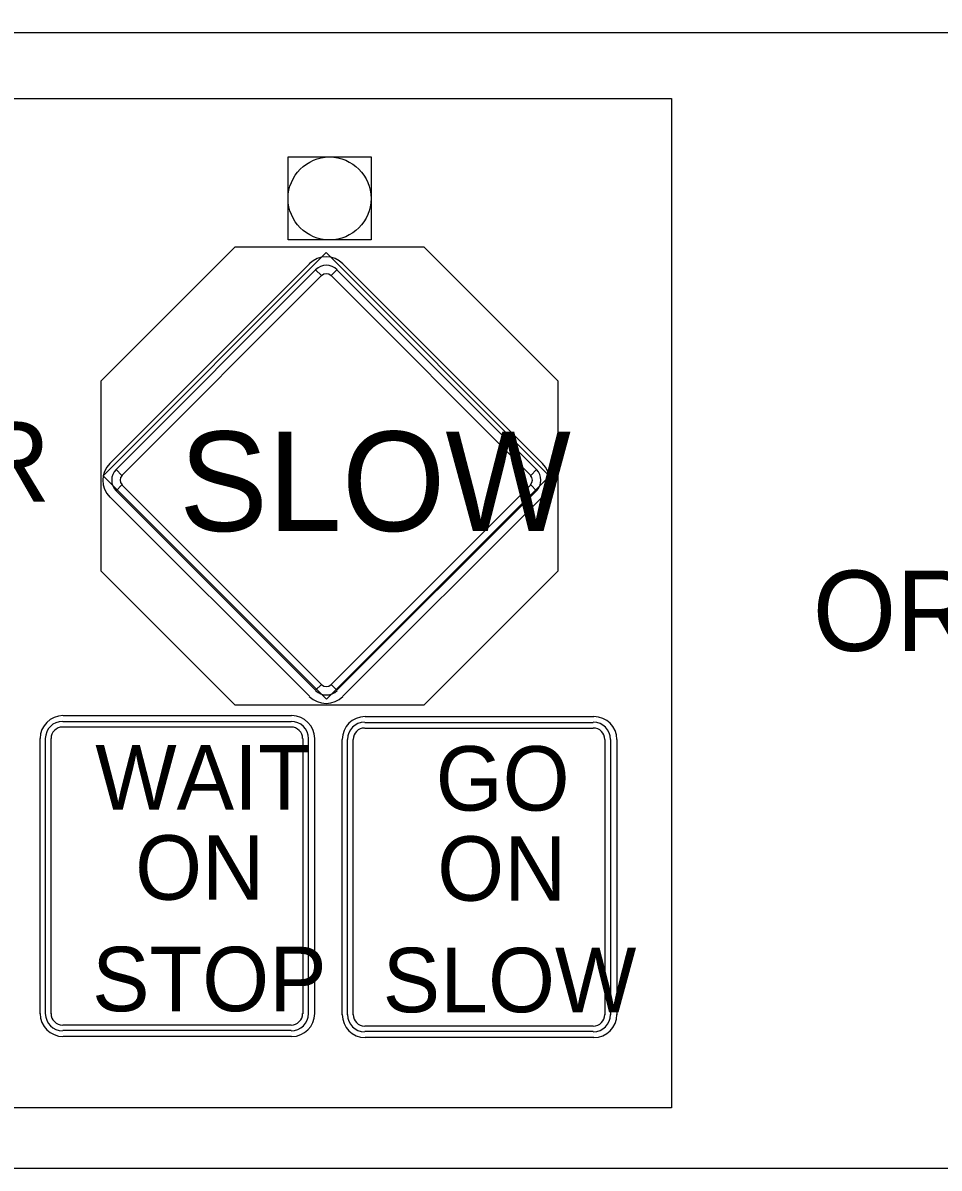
# Model space of a CAD drawing. Extents: x 21.7 to 29.1, y 5.9 to 16.2.
# Drawn here: x 26.612 to 27.525, y 13.017 to 14.157 of the extents above; entities that cross this region are included whole.
import ezdxf

# ---------------------------------------------------------------- set-up
doc = ezdxf.new("R2010")
doc.units = 0
for name, color, linetype in [('DETL-LINE', 7, 'Continuous'), ('DETL-NOTE', 7, 'Continuous'), ('USER-BORD', 7, 'Continuous')]:
    doc.layers.add(name, color=color, linetype=linetype)

msp = doc.modelspace()

# ---------------------------------------------------------------- linework, layer by layer
at = {"layer": 'DETL-LINE'}
for points in [[(25.8041, 13.0169), (28.9793, 13.0169), (28.9793, 14.3329), (25.8041, 14.3329)], [(28.9732, 14.1469), (25.8041, 14.1469), (25.8041, 13.0169), (28.9732, 13.0169)], [(25.8565, 14.0814), (27.2582, 14.0814), (27.2582, 13.0769), (25.8565, 13.0769)], [(26.8764, 14.0232), (26.9589, 14.0232), (26.9589, 13.9407), (26.8764, 13.9407)]]:
    msp.add_lwpolyline(points, close=True, dxfattribs=at)
msp.add_circle((26.9176, 13.9819), 0.0413, dxfattribs=at)
at = {"layer": 'USER-BORD'}
for p, q in [((26.6987, 13.7181), (26.8975, 13.9169)), ((27.1297, 13.7181), (26.9309, 13.9169)), ((26.7049, 13.7122), (26.9037, 13.911)), ((26.9037, 13.911), (26.9096, 13.9051)), ((26.9037, 13.911), (26.9096, 13.9051)), ((26.9191, 13.9051), (26.925, 13.911)), ((26.9191, 13.9051), (26.925, 13.911)), ((26.925, 13.911), (27.1238, 13.7122)), ((26.9096, 13.9051), (26.7108, 13.7063)), ((27.1179, 13.7063), (26.9191, 13.9051)), ((26.7108, 13.7063), (26.7049, 13.7122)), ((26.7049, 13.7122), (26.7108, 13.7063)), ((27.1238, 13.7122), (27.1179, 13.7063)), ((27.1238, 13.7122), (27.1179, 13.7063)), ((26.7108, 13.6968), (26.7049, 13.6909)), ((26.7049, 13.6909), (26.9037, 13.4924)), ((26.9096, 13.4983), (26.7108, 13.6968)), ((26.9191, 13.4983), (27.1179, 13.6968)), ((27.1238, 13.6909), (26.925, 13.4924)), ((27.1179, 13.6968), (27.1238, 13.6909)), ((27.1179, 13.6968), (27.1238, 13.6909)), ((26.6987, 13.685), (26.8975, 13.4865)), ((27.1297, 13.685), (26.9309, 13.4865)), ((26.9037, 13.4924), (26.9096, 13.4983)), ((26.9037, 13.4924), (26.9096, 13.4983)), ((26.925, 13.4924), (26.9191, 13.4983)), ((26.9191, 13.4983), (26.925, 13.4924)), ((26.6518, 13.4614), (26.8793, 13.4614)), ((26.6523, 13.4672), (26.8798, 13.4672)), ((26.9532, 13.4662), (27.1807, 13.4662)), ((26.6518, 13.4559), (26.8793, 13.4559)), ((26.9527, 13.4604), (27.1802, 13.4604)), ((26.9527, 13.4549), (27.1802, 13.4549)), ((26.6294, 13.1705), (26.6294, 13.4446)), ((26.6347, 13.1705), (26.6347, 13.4446)), ((26.6402, 13.1705), (26.6402, 13.4446)), ((26.8909, 13.4446), (26.8909, 13.1705)), ((26.8964, 13.4446), (26.8964, 13.1705)), ((26.9027, 13.4446), (26.9027, 13.1705)), ((26.9303, 13.1695), (26.9303, 13.4436)), ((26.9356, 13.1695), (26.9356, 13.4436)), ((26.941, 13.1695), (26.941, 13.4436)), ((27.1918, 13.4436), (27.1918, 13.1695)), ((27.1973, 13.4436), (27.1973, 13.1695)), ((27.2036, 13.4436), (27.2036, 13.1695)), ((26.8793, 13.1592), (26.6518, 13.1592)), ((26.8793, 13.1537), (26.6518, 13.1537)), ((27.1802, 13.1582), (26.9527, 13.1582)), ((26.8798, 13.1479), (26.6523, 13.1479)), ((27.1802, 13.1528), (26.9527, 13.1528)), ((27.1807, 13.1469), (26.9532, 13.1469))]:
    msp.add_line(p, q, dxfattribs=at)
for points in [[(27.0119, 13.4779), (27.1453, 13.6114), (27.1453, 13.8), (27.0119, 13.9334), (26.8232, 13.9334), (26.6898, 13.8), (26.6898, 13.6114), (26.8232, 13.4779)], [(26.9142, 13.928), (27.1365, 13.7056), (26.9144, 13.4835), (26.692, 13.7058)]]:
    msp.add_lwpolyline(points, close=True, dxfattribs=at)
for centre, radius, start, end in [((26.9142, 13.9001), 0.0237, 45, 135), ((26.9144, 13.9003), 0.0151, 45, 135), ((26.9144, 13.9003), 0.00669, 45, 135), ((26.7155, 13.7014), 0.0237, 134.9987, 224.9987), ((26.7157, 13.7016), 0.0151, 135, 225), ((27.113, 13.7016), 0.0151, 315, 45), ((27.1129, 13.7014), 0.0237, 315.0013, 45.0013), ((26.7157, 13.7016), 0.00669, 135, 225), ((27.113, 13.7016), 0.00669, 315, 45), ((26.9144, 13.5029), 0.00669, 225, 315), ((26.9142, 13.5031), 0.0237, 225, 315), ((26.9144, 13.5029), 0.0151, 225, 315), ((26.6521, 13.4444), 0.0228, 90, 180), ((26.6516, 13.4444), 0.0171, 90, 180), ((26.8794, 13.4444), 0.0171, 0, 90), ((26.88, 13.4444), 0.0228, 0, 90), ((26.953, 13.4435), 0.0228, 90, 180), ((27.1809, 13.4435), 0.0228, 0, 90), ((26.6516, 13.4444), 0.0114, 90, 180), ((26.8794, 13.4444), 0.0114, 0, 90), ((26.9525, 13.4435), 0.0171, 90, 180), ((26.9525, 13.4435), 0.0114, 90, 180), ((27.1803, 13.4435), 0.0171, 0, 90), ((27.1803, 13.4435), 0.0114, 0, 90), ((26.6521, 13.1707), 0.0228, 180, 270), ((26.6516, 13.1707), 0.0171, 180, 270), ((26.6516, 13.1707), 0.0114, 180, 270), ((26.8794, 13.1707), 0.0171, 270, 0), ((26.8794, 13.1707), 0.0114, 270, 0), ((26.88, 13.1707), 0.0228, 270, 0), ((26.953, 13.1697), 0.0228, 180, 270), ((26.9525, 13.1697), 0.0171, 180, 270), ((26.9525, 13.1697), 0.0114, 180, 270), ((27.1803, 13.1697), 0.0171, 270, 0), ((27.1803, 13.1697), 0.0114, 270, 0), ((27.1809, 13.1697), 0.0228, 270, 0)]:
    msp.add_arc(centre, radius, start, end, dxfattribs=at)

# ---------------------------------------------------------------- texts
at = {"layer": 'DETL-NOTE'}
for p in [(26.479, 13.68), (27.3988, 13.5316)]:
    msp.add_text('OR', height=0.08, dxfattribs=at).set_placement(p)
at = {"layer": 'USER-BORD'}
for s, height, p in [('SLOW', 0.09909, (26.7678, 13.6509)), ('WAIT', 0.06415, (26.6843, 13.3737)), ('GO', 0.06415, (27.0233, 13.3727)), ('ON', 0.06415, (26.7239, 13.284)), ('ON', 0.06415, (27.0248, 13.283)), ('STOP', 0.06415, (26.6811, 13.173)), ('SLOW', 0.06415, (26.9705, 13.172))]:
    msp.add_text(s, height=height, dxfattribs=at).set_placement(p)

doc.saveas('drawing.dxf')
